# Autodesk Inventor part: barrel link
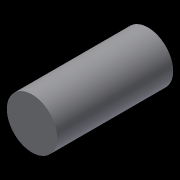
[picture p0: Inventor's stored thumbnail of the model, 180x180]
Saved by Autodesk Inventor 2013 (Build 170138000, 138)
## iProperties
Created: 2013-01
Part Number: barrel link
Material: Generic
Document SubType Name: Modeling
Designer: John
Density: 1 g/cm^3
Author: John
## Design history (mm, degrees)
sketch "Sketch1"
  geometry: C1 r 1.975 at (0, 0); 1 further point
  constraints: 1 centre point, 1 coincident
  dimensions: "d0" = 3.9497 diameter of C1
extrude "Extrusion1" new body sketch "Sketch1" distance "d1" = 9.0932; taper "d2" = 0 deg
body "Solid1"
